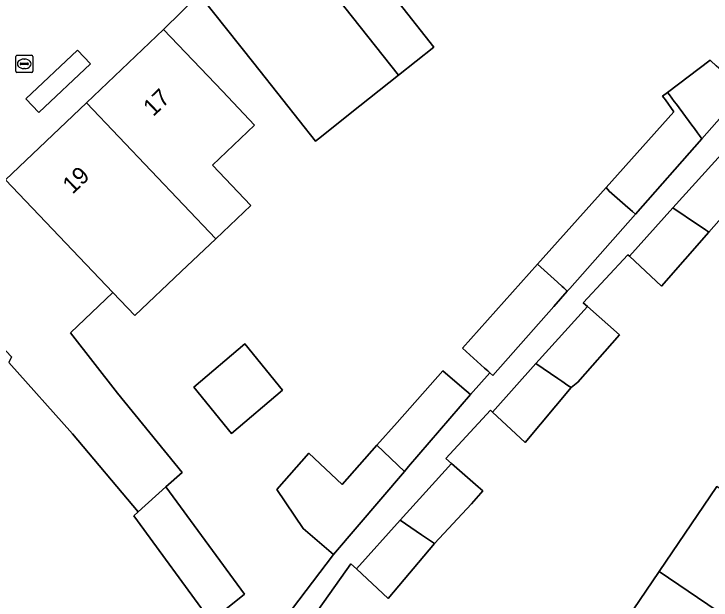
# Model space of a CAD drawing. Extents: x 161881 to 162523, y 381678 to 382381.
# Drawn here: x 162110.45 to 162151.2, y 382053.37 to 382087.64 of the extents above; entities that cross this region are included whole.
import ezdxf

# ---------------------------------------------------------------- set-up
doc = ezdxf.new("R2010")
doc.units = 0
for name, color, linetype in [('IMGEO_Erf', 7, 'Continuous'), ('IMGEO_Groenvoorziening', 7, 'Continuous'), ('IMGEO_Pand', 7, 'Continuous'), ('IMGEO_Pand_nummerreeks', 7, 'Continuous'), ('IMGEO_Rioolput', 7, 'Continuous'), ('IMGEO_Voetpad_open', 7, 'Continuous'), ('IMGEO_Woonerf_open', 7, 'Continuous')]:
    doc.layers.add(name, color=color, linetype=linetype)

msp = doc.modelspace()

# ---------------------------------------------------------------- linework, layer by layer
at = {"layer": 'IMGEO_Erf'}
for points in [[(162132.966, 382088.26), (162135.001, 382085.691), (162132.929, 382084.049), (162130.666, 382082.256), (162128.25, 382080.342), (162128.078, 382080.206), (162126.171, 382082.612), (162124.475, 382084.752), (162121.273, 382088.793), (162119.199, 382086.737), (162122.643, 382083.113), (162124.519, 382081.139), (162122.056, 382078.798), (162124.292, 382076.445), (162122.244, 382074.498), (162120.23, 382072.585), (162117.511, 382070.002), (162116.231, 382071.35), (162113.759, 382069.002), (162116.499, 382065.458), (162120.276, 382060.833), (162119.333, 382059.983), (162123.931, 382053.716), (162121.962, 382052.146), (162117.455, 382058.29), (162117.714, 382058.524), (162113.866, 382063.085), (162110.143, 382067.255)], [(162123.907, 382049.164), (162129.123, 382056.034), (162127.356, 382057.55), (162125.813, 382059.835), (162127.696, 382061.965), (162129.629, 382060.122), (162131.663, 382062.423), (162132.855, 382063.757), (162135.521, 382066.772), (162136.774, 382065.699), (162136.877, 382065.611), (162137.135, 382065.391), (162138.278, 382066.659), (162138.148, 382066.775), (162137.966, 382066.938), (162136.666, 382068.102), (162141.053, 382073.003), (162145.078, 382077.5), (162149.031, 382081.915), (162148.533, 382082.614), (162148.448, 382082.733), (162148.373, 382082.838), (162148.66, 382083.053), (162151.156, 382084.926), (162151.197, 382084.89), (162151.506, 382084.613)], [(162153.833, 382078.011), (162151.078, 382074.877), (162148.312, 382071.73), (162146.429, 382073.474), (162146.338, 382073.558), (162143.732, 382070.744), (162143.975, 382070.53), (162145.852, 382068.874), (162143.414, 382066.101), (162143.023, 382065.801), (162140.33, 382062.593), (162138.417, 382064.363), (162138.304, 382064.468), (162135.697, 382061.652), (162136.024, 382061.364), (162137.276, 382060.259), (162137.58, 382059.991), (162137.856, 382059.748), (162137.749, 382059.626), (162137.199, 382059.001), (162135.037, 382056.675), (162132.333, 382053.465), (162130.465, 382055.195), (162130.144, 382055.492), (162127.585, 382051.883)], [(162144.796, 382050.064), (162148.172, 382055.04), (162151.548, 382060.014)]]:
    msp.add_lwpolyline(points, dxfattribs=at)
msp.add_lwpolyline([(162126.156, 382065.65), (162123.171, 382063.113), (162120.964, 382065.814), (162123.949, 382068.351)], close=True, dxfattribs=at)
at = {"layer": 'IMGEO_Groenvoorziening'}
msp.add_lwpolyline([(162114.914, 382084.729), (162114.156, 382085.528), (162111.147, 382082.674), (162111.905, 382081.875)], close=True, dxfattribs=at)
at = {"layer": 'IMGEO_Pand'}
for points in [[(162135.52, 382090.284), (162130.756, 382096.306), (162126.131, 382092.642), (162132.929, 382084.049), (162135.001, 382085.691), (162132.966, 382088.26)], [(162126.131, 382092.642), (162121.273, 382088.793), (162124.475, 382084.752), (162126.171, 382082.612), (162128.078, 382080.206), (162128.25, 382080.342), (162130.666, 382082.256), (162132.929, 382084.049)], [(162122.244, 382074.498), (162124.292, 382076.445), (162122.056, 382078.798), (162124.519, 382081.139), (162122.643, 382083.113), (162119.199, 382086.737), (162114.682, 382082.444)], [(162148.66, 382083.053), (162148.774, 382082.899), (162148.907, 382082.72), (162149.053, 382082.522), (162149.179, 382082.353), (162150.088, 382081.127), (162150.234, 382080.931), (162150.419, 382080.681), (162150.531, 382080.53), (162150.669, 382080.344), (162153.143, 382083.147), (162153.038, 382083.242), (162152.837, 382083.421), (162152.438, 382083.778), (162151.506, 382084.613), (162151.197, 382084.89), (162151.156, 382084.926)], [(162150.669, 382080.344), (162150.531, 382080.53), (162150.419, 382080.681), (162150.234, 382080.931), (162150.088, 382081.127), (162149.179, 382082.353), (162149.053, 382082.522), (162148.907, 382082.72), (162148.774, 382082.899), (162148.66, 382083.053), (162148.373, 382082.838), (162148.448, 382082.733), (162148.533, 382082.614), (162149.031, 382081.915), (162145.078, 382077.5), (162145.247, 382077.269), (162146.187, 382076.455), (162146.472, 382076.209), (162146.602, 382076.097), (162146.783, 382075.94)], [(162122.244, 382074.498), (162114.682, 382082.444), (162109.951, 382077.948), (162116.231, 382071.35), (162117.511, 382070.002), (162120.23, 382072.585)], [(162151.984, 382079.642), (162148.975, 382076.303), (162150.463, 382075.294), (162150.618, 382075.188), (162150.871, 382075.017), (162150.99, 382074.936), (162151.078, 382074.877), (162153.833, 382078.011), (162153.752, 382078.082), (162153.647, 382078.175), (162153.111, 382078.648)], [(162113.759, 382069.002), (162116.231, 382071.35), (162109.951, 382077.948), (162105.957, 382074.153), (162105.057, 382073.126), (162110.296, 382067.596), (162110.143, 382067.255), (162113.866, 382063.085), (162117.714, 382058.524), (162119.333, 382059.983), (162120.276, 382060.833), (162116.499, 382065.458)], [(162146.783, 382075.94), (162146.602, 382076.097), (162146.472, 382076.209), (162146.187, 382076.455), (162145.247, 382077.269), (162145.078, 382077.5), (162141.053, 382073.003), (162142.219, 382071.952), (162142.496, 382071.702), (162142.589, 382071.618), (162142.8, 382071.428), (162142.945, 382071.592)], [(162151.078, 382074.877), (162150.99, 382074.936), (162150.871, 382075.017), (162150.618, 382075.188), (162150.463, 382075.294), (162148.975, 382076.303), (162146.429, 382073.474), (162148.312, 382071.73)], [(162142.8, 382071.428), (162142.589, 382071.618), (162142.496, 382071.702), (162142.219, 382071.952), (162141.053, 382073.003), (162136.666, 382068.102), (162137.966, 382066.938), (162138.148, 382066.775), (162138.278, 382066.659), (162138.453, 382066.502), (162142.005, 382070.527)], [(162145.852, 382068.874), (162143.975, 382070.53), (162140.968, 382067.194), (162142.248, 382066.326), (162142.488, 382066.163), (162142.839, 382065.925), (162143.023, 382065.801), (162143.414, 382066.101)], [(162120.964, 382065.814), (162123.171, 382063.113), (162126.156, 382065.65), (162123.949, 382068.351)], [(162143.023, 382065.801), (162142.839, 382065.925), (162142.488, 382066.163), (162142.248, 382066.326), (162140.968, 382067.194), (162138.417, 382064.363), (162140.33, 382062.593)], [(162137.135, 382065.391), (162136.877, 382065.611), (162136.774, 382065.699), (162135.521, 382066.772), (162132.855, 382063.757), (162131.663, 382062.423), (162133.279, 382060.883), (162133.522, 382061.176)], [(162133.279, 382060.883), (162131.663, 382062.423), (162129.629, 382060.122), (162127.696, 382061.965), (162125.813, 382059.835), (162127.356, 382057.55), (162129.123, 382056.034)], [(162136.024, 382061.364), (162133.027, 382058.038), (162134.277, 382057.191), (162134.804, 382056.833), (162135.037, 382056.675), (162137.199, 382059.001), (162137.749, 382059.626), (162137.856, 382059.748), (162137.58, 382059.991), (162137.276, 382060.259)], [(162119.333, 382059.983), (162117.714, 382058.524), (162117.455, 382058.29), (162121.962, 382052.146), (162123.931, 382053.716)], [(162148.172, 382055.04), (162154.397, 382050.814), (162157.773, 382055.788), (162151.548, 382060.014)], [(162135.037, 382056.675), (162134.804, 382056.833), (162134.277, 382057.191), (162133.027, 382058.038), (162130.465, 382055.195), (162132.333, 382053.465)], [(162151.021, 382045.838), (162154.397, 382050.814), (162148.172, 382055.04), (162144.796, 382050.064)]]:
    msp.add_lwpolyline(points, close=True, dxfattribs=at)
at = {"layer": 'IMGEO_Rioolput'}
for p, q in [((162110.547, 382084.293), (162110.547, 382085.145)), ((162110.622, 382085.219), (162111.474, 382085.219)), ((162111.548, 382085.145), (162111.548, 382084.293)), ((162110.806, 382084.713), (162110.806, 382084.725)), ((162111.244, 382084.676), (162110.846, 382084.676)), ((162110.849, 382084.762), (162111.247, 382084.762)), ((162111.035, 382084.999), (162111.06, 382084.999)), ((162111.29, 382084.725), (162111.29, 382084.713)), ((162111.058, 382084.439), (162111.033, 382084.439)), ((162111.474, 382084.219), (162110.622, 382084.219))]:
    msp.add_line(p, q, dxfattribs=at)
for points in [[(162110.547, 382084.293), (162110.547, 382085.145)], [(162110.622, 382085.219), (162111.474, 382085.219)], [(162111.548, 382085.145), (162111.548, 382084.293)], [(162111.474, 382084.219), (162110.622, 382084.219)]]:
    msp.add_lwpolyline(points, dxfattribs=at)
for centre, radius, start, end in [((162110.624, 382085.143), 0.0765, 91.552, 178.448), ((162110.624, 382085.143), 0.0765, 91.552, 178.448), ((162111.472, 382085.143), 0.0765, 1.552, 88.448), ((162111.472, 382085.143), 0.0765, 1.552, 88.448), ((162110.846, 382084.722), 0.0403, 85.8775, 175.7526), ((162110.843, 382084.712), 0.0366, 178.938, 274.7102), ((162111.247, 382084.719), 0.043, 264.8664, 352.4533), ((162111.251, 382084.724), 0.0386, 1.7309, 96.639), ((162110.624, 382084.295), 0.0765, 181.552, 268.448), ((162110.624, 382084.295), 0.0765, 181.552, 268.448), ((162111.472, 382084.295), 0.0765, 271.552, 358.448), ((162111.472, 382084.295), 0.0765, 271.552, 358.448)]:
    msp.add_arc(centre, radius, start, end, dxfattribs=at)
for centre, major_axis, ratio, start_param, end_param in [((162111.034, 382084.719), (-0.387, 0.002), 0.722429, 4.712389, 7.853982), ((162111.059, 382084.719), (-0.39, 0.002), 0.717154, 1.570796, 4.712389)]:
    msp.add_ellipse(centre, major_axis=major_axis, ratio=ratio, start_param=start_param, end_param=end_param, dxfattribs=at)
at = {"layer": 'IMGEO_Voetpad_open'}
for points in [[(162153.143, 382083.147), (162150.669, 382080.344), (162146.783, 382075.94), (162142.945, 382071.592), (162142.8, 382071.428), (162142.005, 382070.527), (162138.453, 382066.502), (162138.278, 382066.659), (162137.135, 382065.391), (162133.522, 382061.176), (162133.279, 382060.883), (162129.123, 382056.034), (162123.907, 382049.164)], [(162127.585, 382051.883), (162130.144, 382055.492), (162130.465, 382055.195), (162133.027, 382058.038), (162136.024, 382061.364), (162135.697, 382061.652), (162138.304, 382064.468), (162138.417, 382064.363), (162140.968, 382067.194), (162143.975, 382070.53), (162143.732, 382070.744), (162146.338, 382073.558), (162146.429, 382073.474), (162148.975, 382076.303), (162151.984, 382079.642)]]:
    msp.add_lwpolyline(points, dxfattribs=at)
at = {"layer": 'IMGEO_Woonerf_open'}
for points in [[(162114.682, 382082.444), (162119.199, 382086.737), (162121.273, 382088.793)], [(162082.205, 382046.423), (162085.245, 382050.265), (162087.356, 382052.943), (162087.622, 382053.28), (162088.311, 382054.019), (162092.406, 382058.692), (162096.374, 382063.219), (162100.315, 382067.715), (162105.057, 382073.126), (162105.957, 382074.153), (162109.951, 382077.948), (162114.682, 382082.444)]]:
    msp.add_lwpolyline(points, dxfattribs=at)
msp.add_lwpolyline([(162114.156, 382085.528), (162114.914, 382084.729), (162111.905, 382081.875), (162111.147, 382082.674)], close=True, dxfattribs=at)

# ---------------------------------------------------------------- texts
at = {"layer": 'IMGEO_Pand_nummerreeks'}
for s, p in [('17', (162118.586, 382081.595)), ('19', (162113.872, 382077.058))]:
    msp.add_text(s, height=1, rotation=43.9037, dxfattribs=at).set_placement(p)

doc.saveas('drawing.dxf')
